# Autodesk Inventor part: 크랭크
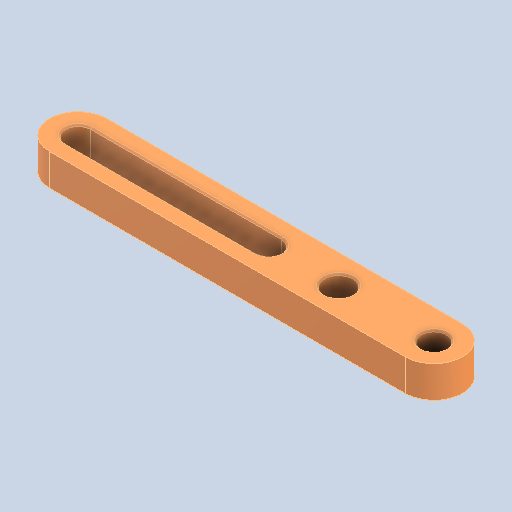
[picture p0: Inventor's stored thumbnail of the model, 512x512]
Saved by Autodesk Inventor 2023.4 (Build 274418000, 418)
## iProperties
Created: 2024-04
Part Number: 크랭크
Material: 알루미늄 6061
Document SubType Name: Modeling
Designer: EDU
Density: 2.71 g/cm^3
Appearance: 기본값
Author: jhkim
Sending System: Autodesk Inventor 2025
Preprocessor: ST-DEVELOPER v20
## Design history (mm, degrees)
node "크랭크1"
node "솔리드2"
node "솔리드1"
